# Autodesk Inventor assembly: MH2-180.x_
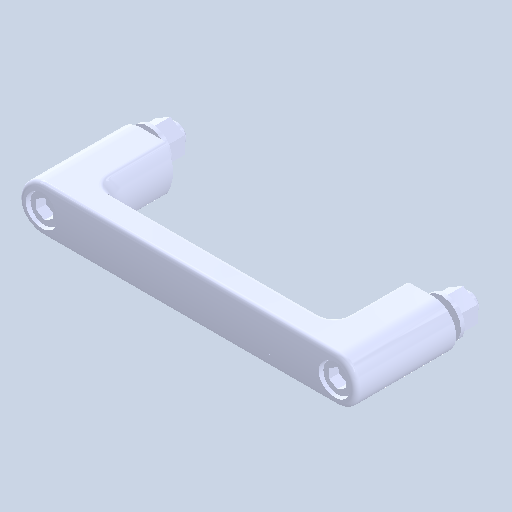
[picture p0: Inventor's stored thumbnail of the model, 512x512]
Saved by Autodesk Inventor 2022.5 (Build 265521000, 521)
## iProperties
Created: 2024-05
Part Number: MH2-180.x_
Document SubType Name: Assembly
Designer: ImaoCorp
Author: ImaoCorp
Sending System: SOLIDWORKS 2022-2022290
MC: AMD64
MC_MODEL: Intel64 Family 6 Model 60 Stepping 3, GenuineIntel
OS: Windows_NT
FRU: Parasolid Version 33.1, build 260,  4-25-2022
FORMAT: text
GUISE: transmit
KEY: FILEMH2-180.x_t
DATE: Fri May 31 16:18:00 2024
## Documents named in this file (4)
- Y:\5.更新分\2024年対応\0530_ROHDE\mh2\mh2-180\MH2-180.x_.iam
- Y:\5.更新分\2024年対応\0530_ROHDE\mh2\mh2-180\MH2-180_01.ipt
- Y:\5.更新分\2024年対応\0530_ROHDE\mh2\mh2-180\MH2-180_02.ipt
- Y:\5.更新分\2024年対応\0530_ROHDE\mh2\mh2-180\MH2-180_03.ipt
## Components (3 placed, 3 different names)
1. MH2-180_01
2. MH2-180_02
3. MH2-180_03
